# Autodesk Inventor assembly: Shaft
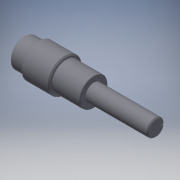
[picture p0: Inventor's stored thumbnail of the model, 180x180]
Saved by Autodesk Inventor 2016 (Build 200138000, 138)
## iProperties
Created: 2015-03
Part Number: Shaft
Document SubType Name: Assembly
Designer: Uglješa
Mass: 353.264 g
Surface Area: 91.0686 cm^2
Volume: 45.0018 cm^3
Density: 7.85 g/cm^3
ClientObjectVersion: 1
Author: Uglješa
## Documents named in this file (2)
- E:\Turbokompr\Assembly1\Design Accelerator\Shaft2.iam
- E:\Turbokompr\Assembly1\Design Accelerator\Shaft2.ipt
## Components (1 placed, 1 different names)
1. Shaft:1
